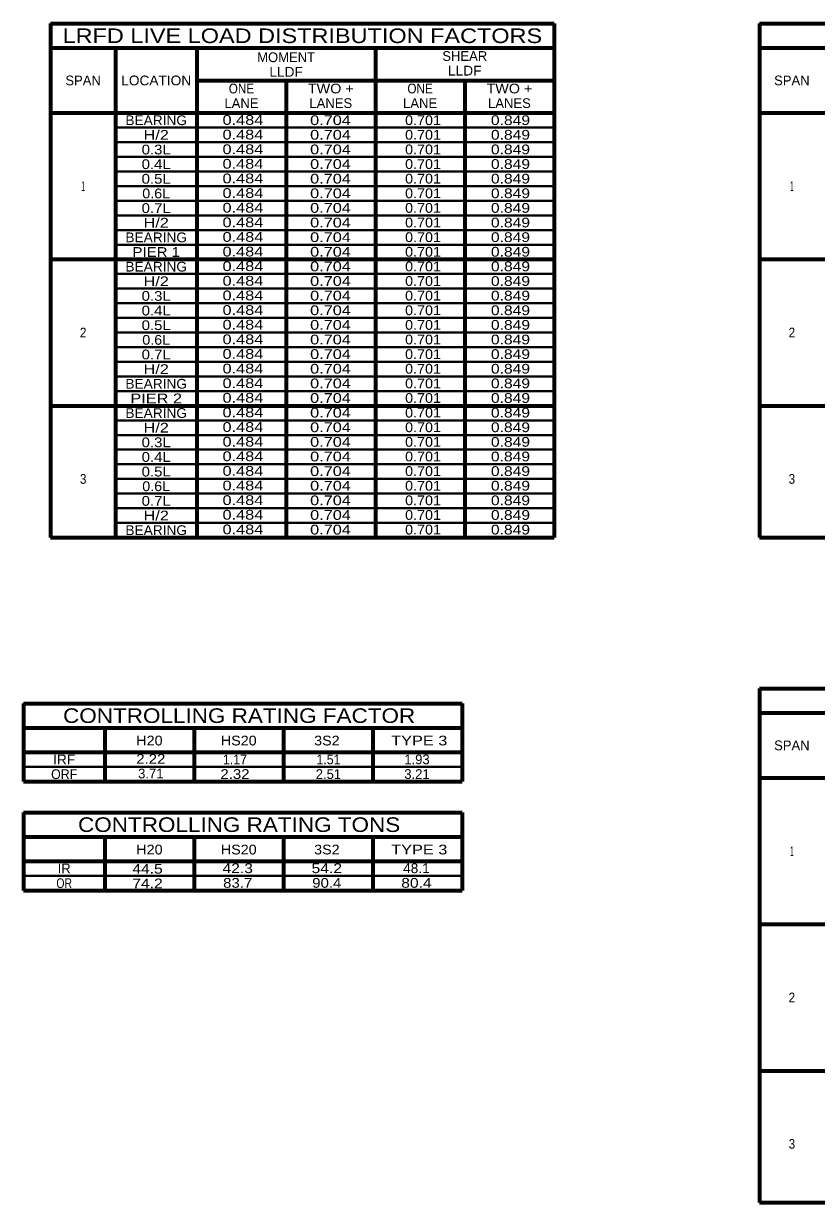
# Model space of a CAD drawing. Extents: x -1807 to -1668, y -81 to 6.
# Drawn here: x -1807.1 to -1758.3, y -66.8 to 5.8 of the extents above; entities that cross this region are included whole.
import ezdxf
from ezdxf.enums import TextEntityAlignment as Align

# ---------------------------------------------------------------- set-up
doc = ezdxf.new("R2010")
doc.units = 0
doc.header["$LTSCALE"] = 0.24
doc.layers.add('1', color=7, linetype='Continuous', lineweight=70)
doc.layers.add('5', color=7, linetype='Continuous', lineweight=40)
doc.layers.add('21', color=7, linetype='Continuous')
doc.layers.add('9', color=7, linetype='Continuous')

msp = doc.modelspace()

# ---------------------------------------------------------------- linework, layer by layer
at = {"layer": '1'}
for p, q in [((-1805.4383, 5.7798), (-1805.4383, -25.8503)), ((-1805.4383, 5.7798), (-1774.4383, 5.7798)), ((-1774.4383, 5.7798), (-1774.4383, -25.8503)), ((-1761.797, 5.7798), (-1761.797, -25.8503)), ((-1761.797, 5.7798), (-1675.797, 5.7798)), ((-1805.4383, 4.2798), (-1774.4383, 4.2798)), ((-1801.4383, 4.2798), (-1801.4383, -25.8503)), ((-1796.4383, 4.2798), (-1796.4383, -25.8503)), ((-1785.4383, 4.2798), (-1785.4383, -25.8503)), ((-1761.797, 4.2798), (-1675.797, 4.2798)), ((-1796.4383, 2.2798), (-1774.4383, 2.2798)), ((-1790.9383, 2.2798), (-1790.9383, -25.8503)), ((-1779.9383, 2.2798), (-1779.9383, -25.8503)), ((-1805.4383, 0.2798), (-1774.4383, 0.2798)), ((-1761.797, 0.2798), (-1675.797, 0.2798)), ((-1805.4383, -8.7306), (-1774.4383, -8.7306)), ((-1761.797, -8.7306), (-1675.797, -8.7306)), ((-1805.4383, -17.741), (-1774.4383, -17.741)), ((-1761.797, -17.741), (-1675.797, -17.741)), ((-1805.4383, -25.8503), (-1774.4383, -25.8503)), ((-1761.797, -25.8503), (-1675.797, -25.8503)), ((-1761.797, -35.1469), (-1675.797, -35.1469)), ((-1761.797, -35.1469), (-1761.797, -66.7771)), ((-1807.1054, -36.0666), (-1780.1054, -36.0666)), ((-1807.1054, -36.0666), (-1807.1054, -40.8687)), ((-1780.1054, -36.0666), (-1780.1054, -40.8687)), ((-1761.797, -36.6469), (-1675.797, -36.6469)), ((-1807.1054, -37.5666), (-1780.1054, -37.5666)), ((-1802.1054, -37.5666), (-1802.1054, -40.8687)), ((-1796.6054, -37.5666), (-1796.6054, -40.8687)), ((-1791.1054, -37.5666), (-1791.1054, -40.8687)), ((-1785.6054, -37.5666), (-1785.6054, -40.8687)), ((-1807.1054, -39.0666), (-1780.1054, -39.0666)), ((-1807.1054, -40.8687), (-1780.1054, -40.8687)), ((-1761.797, -40.6469), (-1675.797, -40.6469)), ((-1807.1054, -42.7758), (-1780.1054, -42.7758)), ((-1807.1054, -42.7758), (-1807.1054, -47.5779)), ((-1780.1054, -42.7758), (-1780.1054, -47.5779)), ((-1807.1054, -44.2758), (-1780.1054, -44.2758)), ((-1802.1054, -44.2758), (-1802.1054, -47.5779)), ((-1796.6054, -44.2758), (-1796.6054, -47.5779)), ((-1791.1054, -44.2758), (-1791.1054, -47.5779)), ((-1785.6054, -44.2758), (-1785.6054, -47.5779)), ((-1807.1054, -45.7758), (-1780.1054, -45.7758)), ((-1807.1054, -47.5779), (-1780.1054, -47.5779)), ((-1761.797, -49.6573), (-1675.797, -49.6573)), ((-1761.797, -58.6677), (-1675.797, -58.6677)), ((-1761.797, -66.7771), (-1675.797, -66.7771))]:
    msp.add_line(p, q, dxfattribs=at)
at = {"layer": '5'}
for p, q in [((-1801.4383, -0.6212), (-1774.4383, -0.6212)), ((-1801.4383, -1.5222), (-1774.4383, -1.5222)), ((-1801.4383, -2.4232), (-1774.4383, -2.4232)), ((-1801.4383, -3.3243), (-1774.4383, -3.3243)), ((-1801.4383, -4.2253), (-1774.4383, -4.2253)), ((-1801.4383, -5.1264), (-1774.4383, -5.1264)), ((-1801.4383, -6.0274), (-1774.4383, -6.0274)), ((-1801.4383, -6.9285), (-1774.4383, -6.9285)), ((-1801.4383, -7.8295), (-1774.4383, -7.8295)), ((-1801.4383, -9.6316), (-1774.4383, -9.6316)), ((-1801.4383, -10.5327), (-1774.4383, -10.5327)), ((-1801.4383, -11.4337), (-1774.4383, -11.4337)), ((-1801.4383, -12.3347), (-1774.4383, -12.3347)), ((-1801.4383, -13.2357), (-1774.4383, -13.2357)), ((-1801.4383, -14.1368), (-1774.4383, -14.1368)), ((-1801.4383, -15.0378), (-1774.4383, -15.0378)), ((-1801.4383, -15.9389), (-1774.4383, -15.9389)), ((-1801.4383, -16.8399), (-1774.4383, -16.8399)), ((-1801.4383, -18.642), (-1774.4383, -18.642)), ((-1801.4383, -19.5431), (-1774.4383, -19.5431)), ((-1801.4383, -20.4441), (-1774.4383, -20.4441)), ((-1801.4383, -21.3452), (-1774.4383, -21.3452)), ((-1801.4383, -22.2462), (-1774.4383, -22.2462)), ((-1801.4383, -23.1472), (-1774.4383, -23.1472)), ((-1801.4383, -24.0482), (-1774.4383, -24.0482)), ((-1801.4383, -24.9493), (-1774.4383, -24.9493)), ((-1807.1054, -39.9676), (-1780.1054, -39.9676)), ((-1807.1054, -46.6769), (-1780.1054, -46.6769))]:
    msp.add_line(p, q, dxfattribs=at)

# ---------------------------------------------------------------- texts
at = {"layer": '1'}
for s, width, p in [('BEARING', 1.05, (-1798.9378, -0.4707)), ('H/2', 1.25, (-1798.938, -1.3717)), ('0.3L', 1.15, (-1798.938, -2.2727)), ('0.4L', 1.15, (-1798.938, -3.1738)), ('0.5L', 1.15, (-1798.938, -4.0748)), ('0.6L', 1.1, (-1798.938, -4.9758)), ('0.7L', 1.15, (-1798.938, -5.8769)), ('H/2', 1.25, (-1798.938, -6.7779)), ('BEARING', 1.05, (-1798.9378, -7.679)), ('PIER 1', 1.15, (-1798.938, -8.58)), ('BEARING', 1.05, (-1798.9378, -9.4811)), ('H/2', 1.25, (-1798.938, -10.3821)), ('0.3L', 1.15, (-1798.938, -11.2832)), ('0.4L', 1.15, (-1798.938, -12.1842)), ('0.5L', 1.15, (-1798.938, -13.0853)), ('0.6L', 1.1, (-1798.938, -13.9863)), ('0.7L', 1.15, (-1798.938, -14.8873)), ('H/2', 1.25, (-1798.938, -15.7883)), ('BEARING', 1.05, (-1798.9378, -16.6894)), ('PIER 2', 1.25, (-1798.938, -17.5904)), ('BEARING', 1.05, (-1798.9378, -18.4915)), ('H/2', 1.25, (-1798.938, -19.3925)), ('0.3L', 1.15, (-1798.938, -20.2936)), ('0.4L', 1.15, (-1798.938, -21.1946)), ('0.5L', 1.15, (-1798.938, -22.0957)), ('0.6L', 1.1, (-1798.938, -22.9967)), ('0.7L', 1.15, (-1798.938, -23.8977)), ('H/2', 1.25, (-1798.938, -24.7987)), ('BEARING', 1.05, (-1798.9378, -25.6998)), ('IRF', 1.05, (-1804.6052, -39.8171)), ('ORF', 0.95, (-1804.6052, -40.7182)), ('OR', 0.8, (-1804.6052, -47.4274))]:
    msp.add_text(s, height=0.6, dxfattribs=dict(at, width=width)).set_placement(p, align=Align.CENTER)
msp.add_text('IR', height=0.6, dxfattribs=at).set_placement((-1804.6052, -46.5263), align=Align.CENTER)
at = {"layer": '21'}
for s, p in [('MOMENT', (-1790.938, 3.408)), ('SHEAR', (-1779.9381, 3.4822)), ('SPAN', (-1803.438, 1.9798)), ('SPAN', (-1759.7969, 1.9798)), ('LANE', (-1793.688, 0.5822)), ('LANES', (-1788.188, 0.5822)), ('LANE', (-1782.688, 0.5822)), ('LANES', (-1777.188, 0.5822)), ('SPAN', (-1759.7968, -38.9469)), ('1.93', (-1782.8801, -39.8121)), ('3.71', (-1799.2705, -40.6784)), ('2.51', (-1788.3324, -40.7121)), ('3.21', (-1782.8801, -40.7121))]:
    msp.add_text(s, height=0.6, dxfattribs=at).set_placement(p, align=Align.CENTER)
for s, width, p in [('LLDF', 1.05, (-1790.938, 2.508)), ('LLDF', 1.05, (-1779.9381, 2.5822)), ('LOCATION', 1.05, (-1798.938, 1.9798)), ('ONE', 0.9, (-1793.688, 1.4822)), ('TWO +', 1.1, (-1788.188, 1.4822)), ('ONE', 0.9, (-1782.688, 1.4822)), ('TWO +', 1.1, (-1777.188, 1.4822)), ('1', 0.4, (-1803.438, -4.5253)), ('1', 0.4, (-1759.7968, -4.5253)), ('2', 0.9, (-1803.4378, -13.5358)), ('2', 0.9, (-1759.7966, -13.5358)), ('3', 0.9, (-1803.4378, -22.5462)), ('3', 0.9, (-1759.7966, -22.5462)), ('H20', 1.1, (-1799.3552, -38.649)), ('HS20', 1.1, (-1793.8552, -38.649)), ('3S2', 1.1, (-1788.4287, -38.649)), ('TYPE 3', 1.25, (-1782.7394, -38.649)), ('2.22', 1.15, (-1799.2706, -39.7784)), ('1.17', 0.95, (-1794.0875, -39.8121)), ('1.51', 0.95, (-1788.3324, -39.8121)), ('2.32', 1.15, (-1794.0876, -40.7121)), ('H20', 1.1, (-1799.3552, -45.3582)), ('HS20', 1.1, (-1793.8552, -45.3582)), ('3S2', 1.1, (-1788.4287, -45.3582)), ('TYPE 3', 1.25, (-1782.7394, -45.3582)), ('1', 0.4, (-1759.7967, -45.4521)), ('44.5', 1.2, (-1799.4725, -46.5432)), ('42.3', 1.2, (-1793.9193, -46.5095)), ('54.2', 1.2, (-1788.4334, -46.5095)), ('48.1', 1.05, (-1782.9138, -46.5095)), ('74.2', 1.2, (-1799.4725, -47.4432)), ('83.7', 1.15, (-1793.9193, -47.4095)), ('90.4', 1.15, (-1788.4334, -47.4095)), ('80.4', 1.2, (-1782.9138, -47.4095)), ('2', 0.9, (-1759.7966, -54.4625)), ('3', 0.9, (-1759.7966, -63.4729))]:
    msp.add_text(s, height=0.6, dxfattribs=dict(at, width=width)).set_placement(p, align=Align.CENTER)
at = {"layer": '9'}
for s, height, width, p in [('LRFD LIVE LOAD DISTRIBUTION FACTORS', 0.9, 1.2, (-1789.9378, 4.5798)), ('0.704', 0.6, 1.25, (-1788.2057, -0.4657)), ('0.701', 0.6, 1.1, (-1782.5077, -0.4657)), ('0.849', 0.6, 1.2, (-1777.1236, -0.4657)), ('0.704', 0.6, 1.25, (-1788.2057, -1.3657)), ('0.701', 0.6, 1.1, (-1782.5077, -1.3657)), ('0.849', 0.6, 1.2, (-1777.1236, -1.3657)), ('0.704', 0.6, 1.25, (-1788.2057, -2.2657)), ('0.701', 0.6, 1.1, (-1782.5077, -2.2657)), ('0.849', 0.6, 1.2, (-1777.1236, -2.2657)), ('0.704', 0.6, 1.25, (-1788.2057, -3.1657)), ('0.701', 0.6, 1.1, (-1782.5077, -3.1657)), ('0.849', 0.6, 1.2, (-1777.1236, -3.1657)), ('0.704', 0.6, 1.25, (-1788.2057, -4.0657)), ('0.701', 0.6, 1.1, (-1782.5077, -4.0657)), ('0.849', 0.6, 1.2, (-1777.1236, -4.0657)), ('0.704', 0.6, 1.25, (-1788.2057, -4.9657)), ('0.701', 0.6, 1.1, (-1782.5077, -4.9657)), ('0.849', 0.6, 1.2, (-1777.1236, -4.9657)), ('0.704', 0.6, 1.25, (-1788.2057, -5.8657)), ('0.701', 0.6, 1.1, (-1782.5077, -5.8657)), ('0.849', 0.6, 1.2, (-1777.1236, -5.8657)), ('0.704', 0.6, 1.25, (-1788.2057, -6.7657)), ('0.701', 0.6, 1.1, (-1782.5077, -6.7657)), ('0.849', 0.6, 1.2, (-1777.1236, -6.7657)), ('0.704', 0.6, 1.25, (-1788.2057, -7.6657)), ('0.701', 0.6, 1.1, (-1782.5077, -7.6657)), ('0.849', 0.6, 1.2, (-1777.1236, -7.6657)), ('0.704', 0.6, 1.25, (-1788.2057, -8.5657)), ('0.701', 0.6, 1.1, (-1782.5077, -8.5657)), ('0.849', 0.6, 1.2, (-1777.1236, -8.5657)), ('0.704', 0.6, 1.25, (-1788.2057, -9.4657)), ('0.701', 0.6, 1.1, (-1782.5077, -9.4657)), ('0.849', 0.6, 1.2, (-1777.1236, -9.4657)), ('0.704', 0.6, 1.25, (-1788.2057, -10.3657)), ('0.701', 0.6, 1.1, (-1782.5077, -10.3657)), ('0.849', 0.6, 1.2, (-1777.1236, -10.3657)), ('0.704', 0.6, 1.25, (-1788.2057, -11.2657)), ('0.701', 0.6, 1.1, (-1782.5077, -11.2657)), ('0.849', 0.6, 1.2, (-1777.1236, -11.2657)), ('0.704', 0.6, 1.25, (-1788.2057, -12.1657)), ('0.701', 0.6, 1.1, (-1782.5077, -12.1657)), ('0.849', 0.6, 1.2, (-1777.1236, -12.1657)), ('0.704', 0.6, 1.25, (-1788.2057, -13.0657)), ('0.701', 0.6, 1.1, (-1782.5077, -13.0657)), ('0.849', 0.6, 1.2, (-1777.1236, -13.0657)), ('0.704', 0.6, 1.25, (-1788.2057, -13.9657)), ('0.701', 0.6, 1.1, (-1782.5077, -13.9657)), ('0.849', 0.6, 1.2, (-1777.1236, -13.9657)), ('0.704', 0.6, 1.25, (-1788.2057, -14.8657)), ('0.701', 0.6, 1.1, (-1782.5077, -14.8657)), ('0.849', 0.6, 1.2, (-1777.1236, -14.8657)), ('0.704', 0.6, 1.25, (-1788.2057, -15.7657)), ('0.701', 0.6, 1.1, (-1782.5077, -15.7657)), ('0.849', 0.6, 1.2, (-1777.1236, -15.7657)), ('0.704', 0.6, 1.25, (-1788.2057, -16.6657)), ('0.701', 0.6, 1.1, (-1782.5077, -16.6657)), ('0.849', 0.6, 1.2, (-1777.1236, -16.6657)), ('0.704', 0.6, 1.25, (-1788.2057, -17.5657)), ('0.701', 0.6, 1.1, (-1782.5077, -17.5657)), ('0.849', 0.6, 1.2, (-1777.1236, -17.5657)), ('0.704', 0.6, 1.25, (-1788.2057, -18.4657)), ('0.701', 0.6, 1.1, (-1782.5077, -18.4657)), ('0.849', 0.6, 1.2, (-1777.1236, -18.4657)), ('0.704', 0.6, 1.25, (-1788.2057, -19.3657)), ('0.701', 0.6, 1.1, (-1782.5077, -19.3657)), ('0.849', 0.6, 1.2, (-1777.1236, -19.3657)), ('0.704', 0.6, 1.25, (-1788.2057, -20.2657)), ('0.701', 0.6, 1.1, (-1782.5077, -20.2657)), ('0.849', 0.6, 1.2, (-1777.1236, -20.2657)), ('0.704', 0.6, 1.25, (-1788.2057, -21.1657)), ('0.701', 0.6, 1.1, (-1782.5077, -21.1657)), ('0.849', 0.6, 1.2, (-1777.1236, -21.1657)), ('0.704', 0.6, 1.25, (-1788.2057, -22.0657)), ('0.701', 0.6, 1.1, (-1782.5077, -22.0657)), ('0.849', 0.6, 1.2, (-1777.1236, -22.0657)), ('0.704', 0.6, 1.25, (-1788.2057, -22.9657)), ('0.701', 0.6, 1.1, (-1782.5077, -22.9657)), ('0.849', 0.6, 1.2, (-1777.1236, -22.9657)), ('0.704', 0.6, 1.25, (-1788.2057, -23.8657)), ('0.701', 0.6, 1.1, (-1782.5077, -23.8657)), ('0.849', 0.6, 1.2, (-1777.1236, -23.8657)), ('0.704', 0.6, 1.25, (-1788.2057, -24.7657)), ('0.701', 0.6, 1.1, (-1782.5077, -24.7657)), ('0.849', 0.6, 1.2, (-1777.1236, -24.7657)), ('0.704', 0.6, 1.25, (-1788.2057, -25.6657)), ('0.701', 0.6, 1.1, (-1782.5077, -25.6657)), ('0.849', 0.6, 1.2, (-1777.1236, -25.6657)), ('CONTROLLING RATING FACTOR', 0.9, 1.15, (-1793.8318, -37.2666)), ('CONTROLLING RATING TONS', 0.9, 1.15, (-1793.8316, -43.9758))]:
    msp.add_text(s, height=height, dxfattribs=dict(at, width=width)).set_placement(p, align=Align.CENTER)
at = {"layer": '9', "width": 1.25}
for p in [(-1794.8543, -0.4527), (-1794.8543, -1.3527), (-1794.8543, -2.2527), (-1794.8543, -3.1527), (-1794.8543, -4.0527), (-1794.8543, -4.9527), (-1794.8543, -5.8527), (-1794.8543, -6.7527), (-1794.8543, -7.6528), (-1794.8543, -8.5527), (-1794.8543, -9.4527), (-1794.8543, -10.3528), (-1794.8543, -11.2527), (-1794.8543, -12.1527), (-1794.8543, -13.0527), (-1794.8543, -13.9527), (-1794.8543, -14.8528), (-1794.8543, -15.7527), (-1794.8543, -16.6528), (-1794.8543, -17.5527), (-1794.8543, -18.4527), (-1794.8543, -19.3528), (-1794.8543, -20.2527), (-1794.8543, -21.1528), (-1794.8543, -22.0527), (-1794.8543, -22.9527), (-1794.8543, -23.8528), (-1794.8543, -24.7527), (-1794.8543, -25.6527)]:
    msp.add_text('0.484', height=0.6, dxfattribs=at).set_placement(p)

doc.saveas('drawing.dxf')
